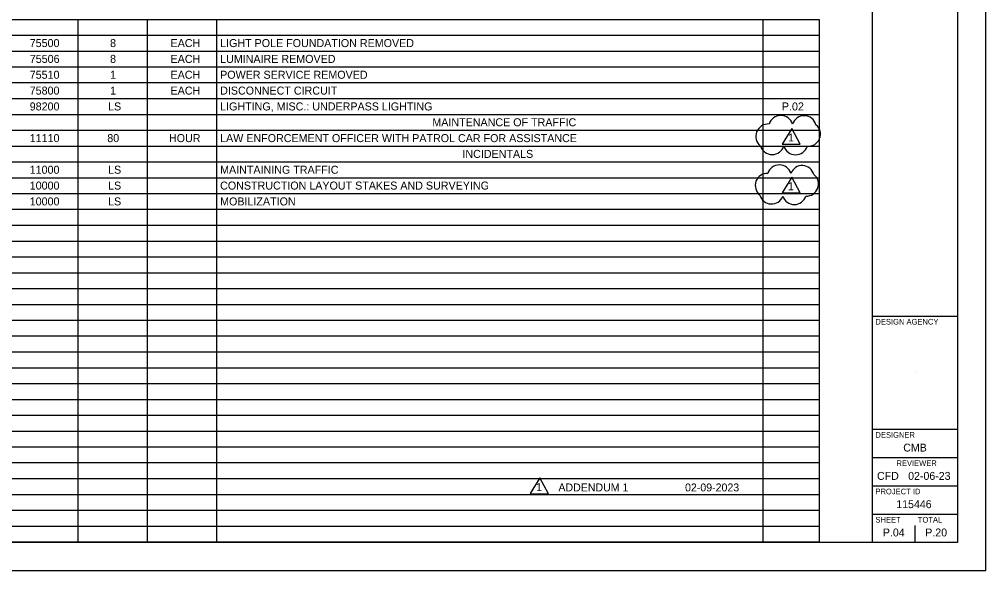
# Model space of a CAD drawing. Extents: x 0 to 34, y 0 to 22.
# Drawn here: x 16.91 to 34, y 0 to 9.75 of the extents above; entities that cross this region are included whole.
import ezdxf

# ---------------------------------------------------------------- set-up
doc = ezdxf.new("R2010")
doc.units = 0
for name, color, linetype in [('Default', 7, 'Continuous'), ('SH_Border', 7, 'Continuous'), ('SH_Cut_Line', 7, 'Continuous'), ('SH_Data', 7, 'Continuous'), ('SH_Text', 7, 'Continuous')]:
    doc.layers.add(name, color=color, linetype=linetype)

msp = doc.modelspace()

# ---------------------------------------------------------------- linework, layer by layer
at = {"layer": 'Default'}
for points in [[(30.571, 7.818), (30.4, 7.539), (30.72, 7.537)], [(30.57, 6.957), (30.399, 6.678), (30.719, 6.676)], [(26.116, 1.639), (25.945, 1.361), (26.265, 1.359)]]:
    msp.add_lwpolyline(points, close=True, dxfattribs=at)
for centre, radius, start, end in [((30.377, 7.83), 0.217, 17.5, 162.5), ((30.789, 7.824), 0.217, 15.8623, 160.8623), ((30.153, 7.676), 0.22, 85.8312, 230.8312), ((30.862, 7.716), 0.215, 265.8599, 50.8599), ((30.223, 7.572), 0.218, 197.5, 342.5), ((30.639, 7.569), 0.218, 196.8512, 341.8512), ((30.137, 6.809), 0.213, 87.2846, 232.2846), ((30.351, 6.958), 0.214, 17.5, 162.5), ((30.755, 6.948), 0.213, 14.7205, 159.7205), ((30.83, 6.834), 0.213, 267.2156, 52.2156), ((30.213, 6.694), 0.213, 194.6403, 339.6403), ((30.616, 6.685), 0.214, 197.6539, 342.6539)]:
    msp.add_arc(centre, radius, start, end, dxfattribs=at)
at = {"layer": 'SH_Border'}
for p, q in [((32, 0.5), (32, 21.5)), ((32, 4.5), (33.5, 4.5)), ((32, 2.5), (33.5, 2.5)), ((32, 2), (33.5, 2)), ((32, 1.5), (33.5, 1.5)), ((32, 1), (33.5, 1))]:
    msp.add_line(p, q, dxfattribs=at)
msp.add_lwpolyline([(1.5, 21.5), (33.5, 21.5), (33.5, 0.5), (1.5, 0.5)], close=True, dxfattribs=at)
at = {"layer": 'SH_Cut_Line'}
msp.add_lwpolyline([(0, 0), (34, 0), (34, 22), (0, 22)], close=True, dxfattribs=at)
at = {"layer": 'SH_Data'}
for p, q in [((32.75, 3.5), (32.75, 3.5)), ((32.75, 0.5), (32.75, 0.8)), ((32.375, 0.675), (32.375, 0.675))]:
    msp.add_line(p, q, dxfattribs=at)
at = {"layer": 'SH_Text'}
for p, q in [((13.49, 9.745), (31.057, 9.745)), ((17.941, 9.745), (17.941, 8.906)), ((19.168, 9.745), (19.168, 8.906)), ((20.395, 9.745), (20.395, 8.906)), ((30.057, 9.745), (30.057, 8.906)), ((31.057, 9.745), (31.057, 8.906)), ((13.49, 9.465), (31.057, 9.465)), ((13.49, 9.185), (31.057, 9.185)), ((13.49, 8.906), (31.057, 8.906)), ((17.941, 8.906), (17.941, 8.346)), ((19.168, 8.906), (19.168, 8.346)), ((20.395, 8.906), (20.395, 8.346)), ((30.057, 8.906), (30.057, 8.346)), ((31.057, 8.906), (31.057, 8.346)), ((13.49, 8.626), (31.057, 8.626)), ((13.49, 8.346), (31.057, 8.346)), ((17.941, 8.346), (17.941, 7.506)), ((19.168, 8.346), (19.168, 7.506)), ((20.395, 8.346), (20.395, 7.506)), ((30.057, 8.346), (30.057, 7.506)), ((31.057, 8.346), (31.057, 7.506)), ((13.49, 8.066), (31.057, 8.066)), ((13.49, 7.786), (31.057, 7.786)), ((13.49, 7.506), (31.057, 7.506)), ((17.941, 7.506), (17.941, 6.946)), ((19.168, 7.506), (19.168, 6.946)), ((20.395, 7.506), (20.395, 6.946)), ((30.057, 7.506), (30.057, 6.946)), ((31.057, 7.506), (31.057, 6.946)), ((13.49, 7.226), (31.057, 7.226)), ((13.49, 6.946), (31.057, 6.946)), ((17.941, 6.946), (17.941, 6.107)), ((19.168, 6.946), (19.168, 6.107)), ((20.395, 6.946), (20.395, 6.107)), ((30.057, 6.946), (30.057, 6.107)), ((31.057, 6.946), (31.057, 6.107)), ((13.49, 6.667), (31.057, 6.667)), ((13.49, 6.387), (31.057, 6.387)), ((13.49, 6.107), (31.057, 6.107)), ((17.941, 6.107), (17.941, 4.987)), ((19.168, 6.107), (19.168, 4.987)), ((20.395, 6.107), (20.395, 4.987)), ((30.057, 6.107), (30.057, 4.987)), ((31.057, 6.107), (31.057, 4.987)), ((13.49, 5.827), (31.057, 5.827)), ((13.49, 5.547), (31.057, 5.547)), ((13.49, 5.267), (31.057, 5.267)), ((13.49, 4.987), (31.057, 4.987)), ((17.941, 4.987), (17.941, 4.707)), ((19.168, 4.987), (19.168, 4.707)), ((20.395, 4.987), (20.395, 4.707)), ((30.057, 4.987), (30.057, 4.707)), ((31.057, 4.987), (31.057, 4.707)), ((13.49, 4.707), (31.057, 4.707)), ((17.941, 4.707), (17.941, 3.588)), ((19.168, 4.707), (19.168, 3.588)), ((20.395, 4.707), (20.395, 3.588)), ((30.057, 4.707), (30.057, 3.588)), ((31.057, 4.707), (31.057, 3.588)), ((13.49, 4.428), (31.057, 4.428)), ((13.49, 4.148), (31.057, 4.148)), ((13.49, 3.868), (31.057, 3.868)), ((13.49, 3.588), (31.057, 3.588)), ((17.941, 3.588), (17.941, 3.308)), ((19.168, 3.588), (19.168, 3.308)), ((20.395, 3.588), (20.395, 3.308)), ((30.057, 3.588), (30.057, 3.308)), ((31.057, 3.588), (31.057, 3.308)), ((13.49, 3.308), (31.057, 3.308)), ((17.941, 3.308), (17.941, 2.189)), ((19.168, 3.308), (19.168, 2.189)), ((20.395, 3.308), (20.395, 2.189)), ((30.057, 3.308), (30.057, 2.189)), ((31.057, 3.308), (31.057, 2.189)), ((13.49, 3.028), (31.057, 3.028)), ((13.49, 2.748), (31.057, 2.748)), ((13.49, 2.468), (31.057, 2.468)), ((13.49, 2.189), (31.057, 2.189)), ((17.941, 2.189), (17.941, 1.909)), ((19.168, 2.189), (19.168, 1.909)), ((20.395, 2.189), (20.395, 1.909)), ((30.057, 2.189), (30.057, 1.909)), ((31.057, 2.189), (31.057, 1.909)), ((13.49, 1.909), (31.057, 1.909)), ((17.941, 1.909), (17.941, 0.789)), ((19.168, 1.909), (19.168, 0.789)), ((20.395, 1.909), (20.395, 0.789)), ((30.057, 1.909), (30.057, 0.789)), ((31.057, 1.909), (31.057, 0.789)), ((13.49, 1.629), (31.057, 1.629)), ((13.49, 1.349), (31.057, 1.349)), ((13.49, 1.069), (31.057, 1.069)), ((13.49, 0.789), (31.057, 0.789)), ((17.941, 0.789), (17.941, 0.509)), ((19.168, 0.789), (19.168, 0.509)), ((20.395, 0.789), (20.395, 0.509)), ((30.057, 0.789), (30.057, 0.509)), ((31.057, 0.789), (31.057, 0.509)), ((13.49, 0.509), (31.057, 0.509))]:
    msp.add_line(p, q, dxfattribs=at)

# ---------------------------------------------------------------- texts
at = {"layer": 'Default'}
for s, p in [('1', (30.504, 7.586)), ('1', (30.503, 6.725)), ('1', (26.048, 1.407)), ('ADDENDUM 1', (26.442, 1.401)), ('02-09-2023', (28.682, 1.401))]:
    msp.add_text(s, height=0.14, dxfattribs=at).set_placement(p)
at = {"layer": 'SH_Data'}
for s, height, p in [('DESIGN AGENCY', 0.1, (32.05, 4.35)), ('DESIGNER', 0.1, (32.05, 2.35)), ('CMB', 0.14, (32.542, 2.105)), ('REVIEWER', 0.1, (32.422, 1.85)), ('CFD', 0.14, (32.078, 1.605)), ('02-06-23', 0.14, (32.629, 1.605)), ('PROJECT ID', 0.1, (32.05, 1.35)), ('115446', 0.14, (32.419, 1.105)), ('SHEET', 0.1, (32.05, 0.85)), ('TOTAL', 0.1, (32.8, 0.85)), ('P.04', 0.14, (32.182, 0.605)), ('P.20', 0.14, (32.932, 0.605))]:
    msp.add_text(s, height=height, dxfattribs=at).set_placement(p)
at = {"layer": 'SH_Text'}
for s, height, p in [('75500', 0.1416, (17.09, 9.255)), ('8', 0.142, (18.511, 9.255)), ('EACH', 0.1416, (19.581, 9.255)), ('LIGHT POLE FOUNDATION REMOVED', 0.1416, (20.458, 9.255)), ('75506', 0.1416, (17.091, 8.975)), ('8', 0.142, (18.511, 8.975)), ('EACH', 0.1416, (19.581, 8.975)), ('LUMINAIRE REMOVED', 0.1416, (20.458, 8.975)), ('75510', 0.1416, (17.09, 8.695)), ('1', 0.142, (18.512, 8.695)), ('EACH', 0.1416, (19.581, 8.695)), ('POWER SERVICE REMOVED', 0.1416, (20.458, 8.695)), ('75800', 0.1416, (17.09, 8.415)), ('1', 0.142, (18.512, 8.415)), ('EACH', 0.1416, (19.581, 8.415)), ('DISCONNECT CIRCUIT', 0.1416, (20.458, 8.415)), ('98200', 0.1416, (17.09, 8.135)), ('LS', 0.1416, (18.476, 8.135)), ('LIGHTING, MISC.: UNDERPASS LIGHTING', 0.1416, (20.458, 8.135)), ('P.02', 0.1416, (30.395, 8.135)), ('MAINTENANCE OF TRAFFIC', 0.1416, (24.212, 7.855)), ('11110', 0.1416, (17.09, 7.575)), ('80', 0.1416, (18.462, 7.575)), ('HOUR', 0.1416, (19.553, 7.575)), ('LAW ENFORCEMENT OFFICER WITH PATROL CAR FOR ASSISTANCE', 0.1416, (20.458, 7.575)), ('INCIDENTALS', 0.1416, (24.744, 7.296)), ('11000', 0.1416, (17.09, 7.016)), ('LS', 0.1416, (18.476, 7.016)), ('MAINTAINING TRAFFIC', 0.1416, (20.458, 7.016)), ('10000', 0.1416, (17.09, 6.736)), ('LS', 0.1416, (18.476, 6.736)), ('CONSTRUCTION LAYOUT STAKES AND SURVEYING', 0.1416, (20.458, 6.736)), ('10000', 0.1416, (17.09, 6.456)), ('LS', 0.1416, (18.476, 6.456)), ('MOBILIZATION', 0.1416, (20.458, 6.456))]:
    msp.add_text(s, height=height, dxfattribs=at).set_placement(p)

doc.saveas('drawing.dxf')
